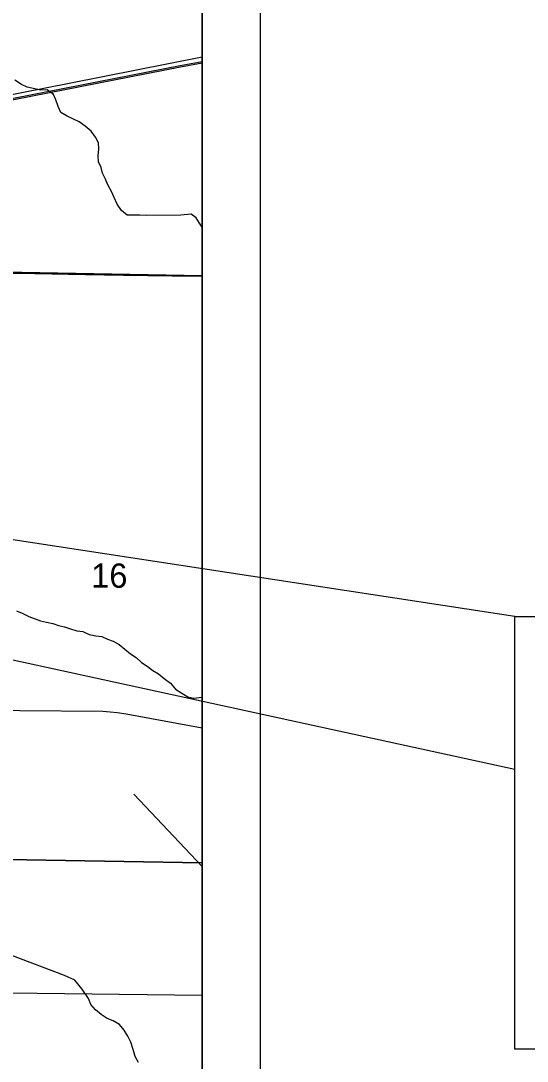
# Model space of a CAD drawing. Extents: x 0 to 42, y 0 to 22.
# Drawn here: x 8.588 to 9.46, y 16.093 to 17.887 of the extents above; entities that cross this region are included whole.
import ezdxf

# ---------------------------------------------------------------- set-up
doc = ezdxf.new("R2010")
doc.units = 0
for name, color, linetype in [('Default', 7, 'Continuous'), ('GM_X_Interchange_Ramps', 7, 'Continuous'), ('GM_X_Minor_River', 7, 'Continuous'), ('GM_X_Rail_Line', 7, 'Continuous'), ('GM_X_Section_Text', 7, 'Continuous'), ('GM_X_State_Route', 7, 'Continuous'), ('GM_X_Township_Road', 7, 'Continuous'), ('GM_X_US_Route', 7, 'Continuous'), ('SH_Data', 7, 'Continuous'), ('SH_Text', 7, 'Continuous')]:
    doc.layers.add(name, color=color, linetype=linetype)

msp = doc.modelspace()

# ---------------------------------------------------------------- linework, layer by layer
at = {"layer": 'Default'}
for points in [[(8.9, 17.4474), (8.9, 18.4589), (8.2652, 18.4704), (8.2465, 17.4593)], [(8.9, 16.4352), (8.9, 17.4474), (8.2465, 17.4593), (8.2267, 16.4466)], [(8.9, 15.4308), (8.9, 16.4352), (8.2267, 16.4466), (8.207, 15.4431)]]:
    msp.add_lwpolyline(points, close=True, dxfattribs=at)
at = {"layer": 'GM_X_Interchange_Ramps'}
msp.add_lwpolyline([(8.9, 14.1), (8.9, 18.4589), (8.6747, 18.462), (8.3265, 18.4669), (8.2646, 18.468), (8.2022, 18.4691), (8.0033, 18.4733), (7.7609, 18.4784), (7.7535, 18.4785), (7.6024, 18.4799), (7.4159, 18.4812), (7.2573, 18.4825), (7.1392, 18.4837)], dxfattribs=at)
at = {"layer": 'GM_X_Minor_River'}
msp.add_line((8.9, 16.4291), (8.7826, 16.5538), dxfattribs=at)
for points in [[(8.7611, 17.56), (8.7537, 17.5712), (8.7486, 17.5827), (8.7439, 17.5927), (8.7377, 17.6042), (8.7334, 17.6141), (8.7286, 17.6245), (8.7262, 17.634), (8.7218, 17.644), (8.7209, 17.6543), (8.7223, 17.6664), (8.7214, 17.677), (8.7166, 17.6866), (8.7092, 17.6966), (8.6984, 17.7052), (8.6884, 17.713), (8.6775, 17.7182), (8.6677, 17.7229), (8.6569, 17.7288), (8.6521, 17.7396), (8.6482, 17.7506), (8.6438, 17.7602), (8.633, 17.7684), (8.622, 17.7675), (8.5986, 17.7725), (8.5889, 17.7773), (8.5773, 17.7847)], [(8.9, 17.5311), (8.8959, 17.538), (8.89, 17.5476), (8.8814, 17.5538), (8.8636, 17.5519), (8.8048, 17.5512), (8.7927, 17.5518), (8.7707, 17.5519), (8.7611, 17.56)], [(8.5802, 16.8696), (8.5903, 16.8656), (8.6016, 16.8601), (8.6219, 16.8528), (8.6317, 16.8504), (8.6427, 16.8482), (8.6528, 16.8446), (8.663, 16.8425), (8.6732, 16.8389), (8.6845, 16.8356), (8.6943, 16.8339), (8.7052, 16.8291), (8.7169, 16.8266), (8.7271, 16.8253), (8.7368, 16.8209), (8.7466, 16.8177), (8.7571, 16.8118), (8.7765, 16.7954), (8.7862, 16.7892), (8.7959, 16.7806), (8.8056, 16.7743), (8.8153, 16.7669), (8.825, 16.7614), (8.8347, 16.7533), (8.8455, 16.7451), (8.8544, 16.735), (8.8653, 16.728), (8.8754, 16.7217), (8.8856, 16.7192), (8.8951, 16.7205), (8.9, 16.7209)], [(8.6631, 16.2411), (8.4943, 16.3049), (8.3357, 16.2511), (8.2312, 16.2931), (8.0898, 16.2891), (8.0345, 16.3354), (7.866, 16.3901), (7.7979, 16.4332), (7.7206, 16.4298), (7.7012, 16.4481), (7.5003, 16.4597), (7.3904, 16.5314), (7.376, 16.5343)], [(8.7904, 16.0908), (8.7846, 16.1016), (8.7811, 16.1134), (8.7775, 16.1264), (8.7724, 16.1364), (8.7658, 16.1468), (8.7577, 16.1568), (8.7468, 16.1627), (8.7367, 16.1671), (8.7262, 16.1741), (8.7165, 16.1816), (8.7084, 16.1912), (8.7044, 16.2015), (8.6937, 16.2177), (8.6805, 16.2333), (8.6631, 16.2411)]]:
    msp.add_lwpolyline(points, dxfattribs=at)
at = {"layer": 'GM_X_Rail_Line'}
for points in [[(2.1, 16.459), (2.2129, 16.4808), (2.5454, 16.5465), (3.2154, 16.6797), (3.8608, 16.8081), (4.4734, 16.9293), (4.9678, 17.0293), (5.6609, 17.1675), (6.33, 17.2984), (6.9548, 17.4275), (7.5722, 17.5495), (8.2054, 17.6814), (8.8625, 17.8098), (8.9, 17.8172)], [(2.1, 16.4567), (2.2123, 16.4784), (2.5452, 16.5433), (3.215, 16.6775), (3.8612, 16.8058), (4.4739, 16.927), (4.9682, 17.0271), (5.6614, 17.1653), (6.3305, 17.2961), (6.9553, 17.4252), (7.5727, 17.5472), (8.2058, 17.6791), (8.8629, 17.8076), (8.9, 17.8149)], [(4.4738, 16.9443), (5.2911, 17.1083), (5.3521, 17.1586), (5.3953, 17.2101), (5.4468, 17.276), (5.4779, 17.3324), (5.5342, 17.3923), (5.5893, 17.4474), (5.618, 17.4689), (5.6635, 17.4809), (6.1368, 17.4838), (6.5418, 17.4827), (6.748, 17.4796), (7.1583, 17.4796), (7.645, 17.5773), (8.6737, 17.7802), (8.9, 17.8248)], [(4.4607, 16.2608), (4.6655, 16.258), (5.6831, 16.252), (6.101, 16.2418), (7.4287, 16.222), (8.568, 16.211), (8.9, 16.2074)]]:
    msp.add_lwpolyline(points, dxfattribs=at)
at = {"layer": 'GM_X_State_Route'}
msp.add_lwpolyline([(8.2466, 17.4576), (8.326, 17.456), (8.5654, 17.452), (8.612, 17.4513), (8.6991, 17.4497), (8.7644, 17.4488), (8.8483, 17.4476), (8.9, 17.4471)], dxfattribs=at)
at = {"layer": 'GM_X_Township_Road'}
msp.add_lwpolyline([(8.2323, 16.7021), (8.2436, 16.702), (8.253, 16.702), (8.3152, 16.7014), (8.4491, 16.6999), (8.586, 16.6979), (8.7293, 16.6966), (8.7417, 16.6959), (8.754, 16.6946), (8.7694, 16.6922), (8.9, 16.6683)], dxfattribs=at)
at = {"layer": 'GM_X_US_Route'}
msp.add_lwpolyline([(8.2466, 17.4576), (8.326, 17.456), (8.5654, 17.452), (8.612, 17.4513), (8.6991, 17.4497), (8.7644, 17.4488), (8.8483, 17.4476), (8.9, 17.4471)], dxfattribs=at)
at = {"layer": 'SH_Data'}
for p, q in [((9, 21), (9, 14)), ((8.9, 20.9), (8.9, 14.1))]:
    msp.add_line(p, q, dxfattribs=at)
at = {"layer": 'SH_Text'}
for points in [[(9.439, 16.8599), (5.3926, 17.4787), (9.439, 16.5971)], [(9.439, 16.8599), (10.9983, 16.8599), (10.9983, 16.1138), (9.439, 16.1138)]]:
    msp.add_lwpolyline(points, close=True, dxfattribs=at)

# ---------------------------------------------------------------- texts
at = {"layer": 'GM_X_Section_Text'}
msp.add_text('16', height=0.04186, rotation=0, dxfattribs=at).set_placement((8.7091, 16.9096))

doc.saveas('drawing.dxf')
